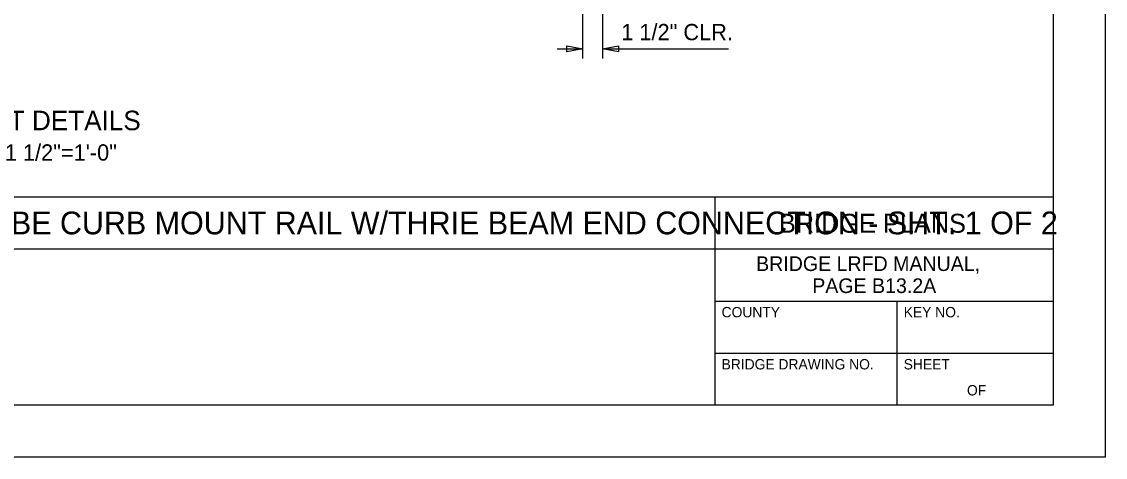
# Model space of a CAD drawing. Extents: x 0 to 45.3, y 0 to 31.4.
# Drawn here: x 31.45 to 45.33, y 0 to 5.58 of the extents above; entities that cross this region are included whole.
import ezdxf

# ---------------------------------------------------------------- set-up
doc = ezdxf.new("R2010")
doc.units = 0
for name, color, linetype in [('BORDER_ANNO_Cutsheet', 7, 'Continuous'), ('BRDG_ANNO_Anno-Sheet', 7, 'Continuous'), ('BRDG_ANNO_General-Notes', 7, 'Continuous')]:
    doc.layers.add(name, color=color, linetype=linetype)

msp = doc.modelspace()

# ---------------------------------------------------------------- linework, layer by layer
at = {"layer": 'BORDER_ANNO_Cutsheet'}
msp.add_lwpolyline([(0, 29.333), (45.333, 29.333), (45.333, 0), (0, 0)], close=True, dxfattribs=at)
at = {"layer": 'BRDG_ANNO_Anno-Sheet'}
for p, q in [((25.667, 3.333), (44.667, 3.333)), ((40.333, 0.667), (40.333, 3.333)), ((29.667, 2.667), (40.333, 2.667)), ((40.333, 2.667), (44.667, 2.667)), ((40.333, 2), (44.667, 2)), ((42.667, 0.667), (42.667, 2)), ((40.333, 1.333), (44.667, 1.333))]:
    msp.add_line(p, q, dxfattribs=at)
msp.add_lwpolyline([(2, 28.667), (44.667, 28.667), (44.667, 0.667), (2, 0.667)], close=True, dxfattribs=at)
at = {"layer": 'BRDG_ANNO_General-Notes'}
for p, q in [((38.639, 5.104), (38.639, 5.776)), ((38.889, 5.754), (38.889, 5.104)), ((38.308, 5.229), (38.639, 5.229)), ((38.432, 5.191), (38.432, 5.268)), ((38.432, 5.268), (38.639, 5.229)), ((38.639, 5.229), (38.432, 5.191)), ((38.889, 5.229), (39.096, 5.268)), ((38.889, 5.229), (40.505, 5.229)), ((39.096, 5.191), (38.889, 5.229)), ((39.096, 5.268), (39.096, 5.191))]:
    msp.add_line(p, q, dxfattribs=at)

# ---------------------------------------------------------------- texts
at = {"layer": 'BRDG_ANNO_Anno-Sheet'}
for s, height, p in [('TWO-TUBE CURB MOUNT RAIL W/THRIE BEAM END CONNECTION - SHT. 1 OF 2', 0.29167, (29.751, 2.854)), ('BRIDGE PLANS', 0.2425, (41.151, 2.875)), ('BRIDGE LRFD MANUAL,', 0.1875, (40.859, 2.385)), ('PAGE B13.2A', 0.1875, (41.578, 2.103)), ('COUNTY', 0.1325, (40.417, 1.792)), ('KEY NO.', 0.1325, (42.75, 1.792)), ('BRIDGE DRAWING NO.', 0.1325, (40.417, 1.125)), ('SHEET', 0.1325, (42.75, 1.125)), ('OF', 0.1325, (43.561, 0.792))]:
    msp.add_text(s, height=height, dxfattribs=at).set_placement(p)
at = {"layer": 'BRDG_ANNO_General-Notes'}
for s, height, p in [('1 1/2" CLR.', 0.20833, (39.131, 5.339)), ('POST DETAILS', 0.25, (30.578, 4.187)), ('1 1/2"=1\'-0"', 0.20833, (31.233, 3.798))]:
    msp.add_text(s, height=height, dxfattribs=at).set_placement(p)

doc.saveas('drawing.dxf')
